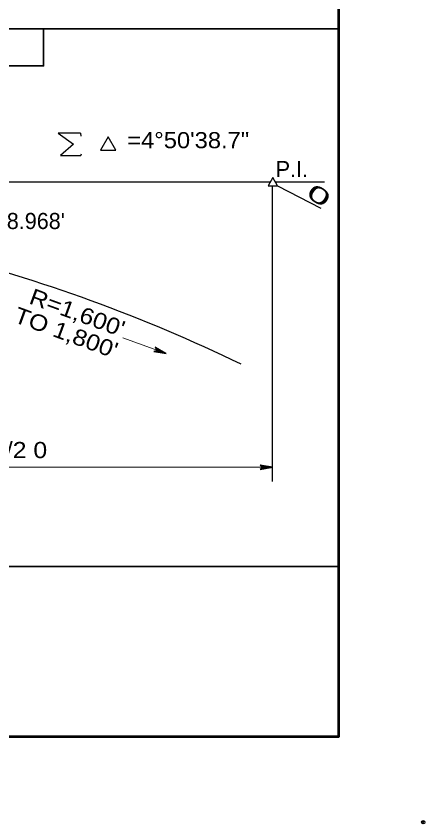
# Model space of a CAD drawing. Extents: x -0.744 to -0.069, y 2.93 to 3.814.
# Drawn here: x -0.3 to -0.0691, y 2.9297 to 3.386 of the extents above; entities that cross this region are included whole.
import ezdxf
from ezdxf.enums import TextEntityAlignment as Align

# ---------------------------------------------------------------- set-up
doc = ezdxf.new("R2010")
doc.units = 0
doc.header["$LTSCALE"] = 0.0036
doc.header["$PDMODE"] = 32
doc.header["$PDSIZE"] = 0.0018
doc.layers.add('1', color=7, linetype='Continuous', lineweight=25)
doc.layers.add('24', color=7, linetype='Continuous', lineweight=25)

msp = doc.modelspace()

# ---------------------------------------------------------------- linework, layer by layer
at = {"layer": '1', "lineweight": 35}
for p, q in [((-0.701192, 3.378767), (-0.117858, 3.378767)), ((-0.701192, 3.075117), (-0.117858, 3.075117))]:
    msp.add_line(p, q, dxfattribs=at)
at = {"layer": '1'}
for p, q in [((-0.263625, 3.319975), (-0.2634, 3.318125)), ((-0.2634, 3.307225), (-0.263158, 3.30815)), ((-0.687225, 3.292475), (-0.156392, 3.292475)), ((-0.153792, 3.292442), (-0.1259, 3.292442)), ((-0.155358, 3.290175), (-0.155358, 3.123183)), ((-0.152392, 3.290175), (-0.127875, 3.27745))]:
    msp.add_line(p, q, dxfattribs=at)
at = {"layer": '1', "lineweight": 13}
msp.add_line((-0.215367, 3.195383), (-0.239667, 3.204225), dxfattribs=at)
at = {"layer": '1', "lineweight": 53}
msp.add_lwpolyline([(-0.701192, 3.770433), (-0.117858, 3.770433), (-0.117858, 2.978767), (-0.701192, 2.978767)], close=True, dxfattribs=at)
at = {"layer": '1', "lineweight": 35}
msp.add_lwpolyline([(-0.284525, 3.378767), (-0.284525, 3.357933), (-0.534525, 3.357933), (-0.534525, 3.378767)], dxfattribs=at)
at = {"layer": '1'}
msp.add_lwpolyline([(-0.263625, 3.319975), (-0.276367, 3.319975), (-0.267567, 3.313717), (-0.274983, 3.307225), (-0.2634, 3.307225)], dxfattribs=at)
for points in [[(-0.248025, 3.317842), (-0.252433, 3.310208), (-0.243625, 3.310208)], [(-0.157708, 3.290175), (-0.152392, 3.290175), (-0.155058, 3.294783)]]:
    msp.add_lwpolyline(points, close=True, dxfattribs=at)
at = {"layer": '1', "lineweight": 13}
msp.add_lwpolyline([(-0.688692, 3.131108), (-0.530392, 3.131108), (-0.155275, 3.131108)], dxfattribs=at)
at = {"layer": '1'}
msp.add_arc((-0.578109, 2.347247), 0.934581, 64.30561, 75.59895, dxfattribs=at)
msp.add_point((-0.070025, 2.930567), dxfattribs=at)
at = {"layer": '24'}
for points in [[(-0.215367, 3.195383), (-0.221458, 3.1989), (-0.220325, 3.197183), (-0.222258, 3.196608), (-0.215367, 3.195383), (-0.2158, 3.195525), (-0.221308, 3.19875), (-0.220208, 3.197125), (-0.221958, 3.1966), (-0.216042, 3.195592), (-0.21625, 3.195708), (-0.220975, 3.198442), (-0.220175, 3.197117), (-0.221658, 3.196658), (-0.21635, 3.195742), (-0.216575, 3.195783), (-0.2207, 3.198192), (-0.220125, 3.197117), (-0.221292, 3.196642), (-0.217208, 3.196017), (-0.217575, 3.19615), (-0.220433, 3.197908), (-0.220042, 3.197108), (-0.220925, 3.196692), (-0.217625, 3.196208), (-0.217967, 3.19635), (-0.22015, 3.1976), (-0.219867, 3.196983), (-0.220508, 3.196717), (-0.218292, 3.19645), (-0.218608, 3.1966), (-0.219908, 3.197375), (-0.219792, 3.196975), (-0.2203, 3.196767), (-0.218792, 3.196633), (-0.219625, 3.197175), (-0.219583, 3.196883), (-0.220075, 3.196775), (-0.219033, 3.196683), (-0.219575, 3.19705), (-0.2194, 3.196758), (-0.219725, 3.19675), (-0.219375, 3.196825), (-0.219517, 3.196917)], [(-0.155275, 3.131108), (-0.162208, 3.132333), (-0.16055, 3.131108), (-0.162167, 3.1299), (-0.155275, 3.131108), (-0.155733, 3.1311), (-0.162008, 3.132242), (-0.160417, 3.131092), (-0.161892, 3.13), (-0.155983, 3.131075), (-0.156217, 3.131108), (-0.161592, 3.132067), (-0.160383, 3.131092), (-0.161625, 3.13015), (-0.156317, 3.131108), (-0.15655, 3.131075), (-0.16125, 3.131925), (-0.160333, 3.131108), (-0.161267, 3.130267), (-0.157217, 3.131075), (-0.157608, 3.131075), (-0.1609, 3.13175), (-0.160258, 3.131125), (-0.16095, 3.130442), (-0.157683, 3.131108), (-0.15805, 3.131133), (-0.160525, 3.13155), (-0.16005, 3.131075), (-0.160567, 3.1306), (-0.158392, 3.131108), (-0.158742, 3.131142), (-0.160225, 3.131425), (-0.159983, 3.131092), (-0.160383, 3.130725), (-0.158917, 3.131108), (-0.159892, 3.131342), (-0.15975, 3.131075), (-0.160175, 3.130808), (-0.159167, 3.131075), (-0.1598, 3.131233), (-0.159533, 3.131025), (-0.159842, 3.1309), (-0.159533, 3.131092), (-0.159692, 3.131125)]]:
    msp.add_lwpolyline(points, dxfattribs=at)

# ---------------------------------------------------------------- texts
at = {"layer": '1'}
for s, width, p in [('=4°50\'38.7"', 1.1, (-0.202813, 3.3114)), ('T=(R+Y) TAN 1/2 0', 1.15, (-0.342833, 3.136317))]:
    msp.add_text(s, height=0.009108, dxfattribs=dict(at, width=width)).set_placement(p, align=Align.CENTER)
msp.add_text('P.I.', height=0.009108, dxfattribs=at).set_placement((-0.144242, 3.29505), align=Align.CENTER)
for s, rotation, width, p in [('0', 326.776, 1.9, (-0.131458, 3.280929)), ("R=1,600'", 339.931, 1.15, (-0.267021, 3.214237)), ("TO 1,800'", 339.931, 1.15, (-0.273329, 3.202917))]:
    msp.add_text(s, height=0.009108, rotation=rotation, dxfattribs=dict(at, width=width)).set_placement(p, align=Align.CENTER)
msp.add_text("8.968'", height=0.009108, dxfattribs=at).set_placement((-0.305317, 3.265725))

doc.saveas('drawing.dxf')
